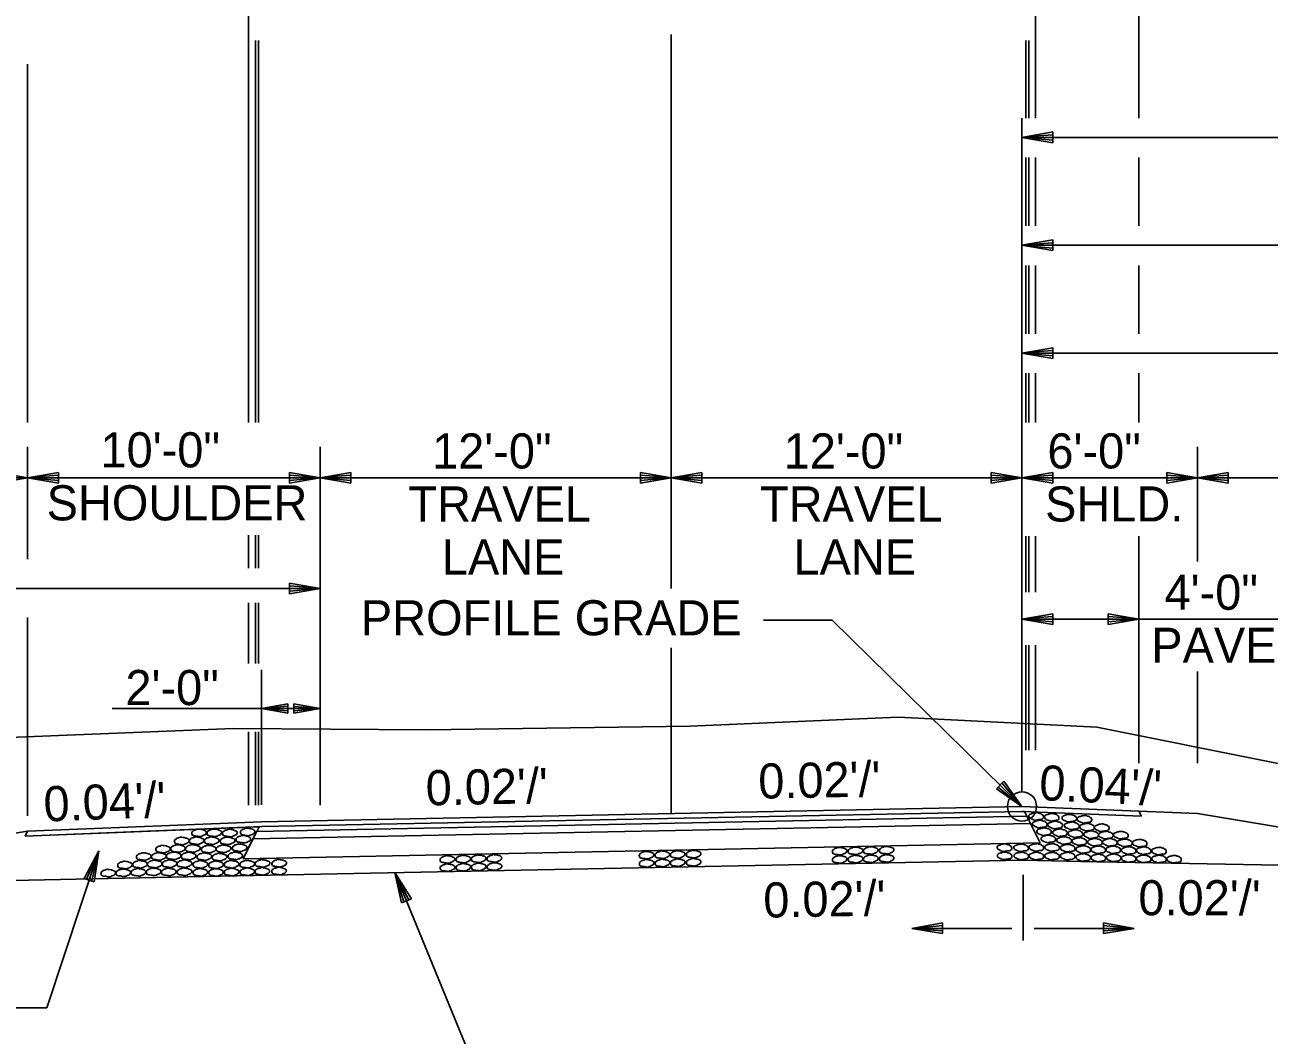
# Model space of a CAD drawing. Extents: x 1734743 to 1735935, y 759845 to 763831.
# Drawn here: x 1735683.61 to 1735726.15, y 763223.34 to 763257.86 of the extents above; entities that cross this region are included whole.
import ezdxf

# ---------------------------------------------------------------- set-up
doc = ezdxf.new("R2010")
doc.units = 0
for name, color, linetype in [('1', 7, 'Continuous'), ('19', 7, 'Continuous'), ('8', 7, 'Continuous'), ('Level 1', 7, 'Continuous'), ('R_Prop Surface', 7, 'Continuous')]:
    doc.layers.add(name, color=color, linetype=linetype)

# ---------------------------------------------------------------- blocks, each defined once
blk = doc.blocks.new('TM')
at = {"layer": '8'}
for p, q in [((-120.309, 21.181), (-119.787, -20.829)), ((0, 0), (-120.309, 21.181)), ((-31.382, 2.945), (-120.176, 10.512)), ((-119.787, -20.829), (0, 0)), ((-119.911, -10.826), (-31.307, -3.057))]:
    blk.add_line(p, q, dxfattribs=at)
blk = doc.blocks.new('ROCKS')
at = {"layer": '1'}
blk.add_spline([(0.013, 0.06), (0.053, 0.053), (0.107, 0.033), (0.133, 0.013), (0.133, -0.007), (0.12, -0.033), (0.107, -0.04), (0.073, -0.053), (0.033, -0.067), (0.013, -0.067), (-0.02, -0.06), (-0.06, -0.053), (-0.087, -0.047), (-0.113, -0.02), (-0.113, -0.007), (-0.107, 0.02), (-0.087, 0.033), (-0.067, 0.047), (-0.033, 0.053), (-0.02, 0.06), (0.013, 0.06)], degree=3, dxfattribs=at)

msp = doc.modelspace()

# ---------------------------------------------------------------- linework, layer by layer
at = {"layer": '19'}
for p, q in [((1735721.698, 763254.679), (1735721.698, 763274.832)), ((1735691.257, 763244.271), (1735691.257, 763259.426)), ((1735718.162, 763254.679), (1735718.162, 763259.426)), ((1735705.701, 763238.596), (1735705.701, 763257.533)), ((1735691.486, 763244.271), (1735691.486, 763257.334)), ((1735691.59, 763244.271), (1735691.59, 763257.334)), ((1735717.832, 763254.679), (1735717.832, 763257.334)), ((1735717.936, 763254.679), (1735717.936, 763257.334)), ((1735683.701, 763244.271), (1735683.701, 763256.522)), ((1735717.701, 763246.647), (1735717.701, 763254.679)), ((1735718.751, 763254.204), (1735717.701, 763254.02)), ((1735718.751, 763254.107), (1735717.981, 763254.046)), ((1735718.751, 763253.836), (1735718.751, 763254.204)), ((1735717.701, 763254.02), (1735797.701, 763254.02)), ((1735717.701, 763254.02), (1735718.751, 763253.836)), ((1735717.981, 763253.994), (1735718.751, 763253.924)), ((1735717.832, 763250.993), (1735717.832, 763253.332)), ((1735717.936, 763250.993), (1735717.936, 763253.332)), ((1735718.162, 763250.993), (1735718.162, 763253.332)), ((1735721.698, 763250.993), (1735721.698, 763253.332)), ((1735718.751, 763250.517), (1735717.701, 763250.333)), ((1735717.701, 763250.333), (1735718.751, 763250.149)), ((1735717.701, 763250.333), (1735757.701, 763250.333)), ((1735718.751, 763250.421), (1735717.981, 763250.359)), ((1735717.981, 763250.307), (1735718.751, 763250.237)), ((1735718.751, 763250.149), (1735718.751, 763250.517)), ((1735717.832, 763247.306), (1735717.832, 763249.645)), ((1735717.936, 763247.306), (1735717.936, 763249.645)), ((1735718.162, 763247.306), (1735718.162, 763249.645)), ((1735721.698, 763247.306), (1735721.698, 763249.645)), ((1735718.751, 763246.83), (1735717.701, 763246.647)), ((1735717.701, 763231.674), (1735717.701, 763246.647)), ((1735717.701, 763246.647), (1735718.751, 763246.463)), ((1735717.701, 763246.647), (1735747.701, 763246.647)), ((1735718.751, 763246.734), (1735717.981, 763246.673)), ((1735717.981, 763246.62), (1735718.751, 763246.55)), ((1735718.751, 763246.463), (1735718.751, 763246.83)), ((1735717.832, 763244.271), (1735717.832, 763245.958)), ((1735717.936, 763244.271), (1735717.936, 763245.958)), ((1735718.162, 763244.271), (1735718.162, 763245.958)), ((1735721.698, 763244.271), (1735721.698, 763245.958)), ((1735683.701, 763239.604), (1735683.701, 763243.437)), ((1735693.701, 763231.194), (1735693.701, 763243.437)), ((1735723.701, 763239.527), (1735723.701, 763243.437)), ((1735672.289, 763242.387), (1735683.701, 763242.387)), ((1735683.701, 763242.387), (1735682.651, 763242.571)), ((1735682.651, 763242.203), (1735683.701, 763242.387)), ((1735684.751, 763242.571), (1735683.701, 763242.387)), ((1735683.701, 763242.387), (1735693.701, 763242.387)), ((1735683.701, 763242.387), (1735684.751, 763242.203)), ((1735684.751, 763242.474), (1735683.981, 763242.413)), ((1735683.981, 763242.361), (1735684.751, 763242.291)), ((1735684.751, 763242.203), (1735684.751, 763242.571)), ((1735692.651, 763242.571), (1735692.651, 763242.203)), ((1735693.701, 763242.387), (1735692.651, 763242.571)), ((1735693.421, 763242.413), (1735692.651, 763242.475)), ((1735692.651, 763242.203), (1735693.701, 763242.387)), ((1735692.651, 763242.291), (1735693.421, 763242.361)), ((1735694.751, 763242.571), (1735693.701, 763242.387)), ((1735693.701, 763242.387), (1735705.701, 763242.387)), ((1735693.701, 763242.387), (1735694.751, 763242.203)), ((1735694.751, 763242.474), (1735693.981, 763242.413)), ((1735693.981, 763242.361), (1735694.751, 763242.291)), ((1735694.751, 763242.203), (1735694.751, 763242.571)), ((1735704.651, 763242.571), (1735704.651, 763242.203)), ((1735705.701, 763242.387), (1735704.651, 763242.571)), ((1735705.421, 763242.413), (1735704.651, 763242.475)), ((1735704.651, 763242.203), (1735705.701, 763242.387)), ((1735704.651, 763242.291), (1735705.421, 763242.361)), ((1735706.751, 763242.571), (1735705.701, 763242.387)), ((1735705.701, 763242.387), (1735717.701, 763242.387)), ((1735705.701, 763242.387), (1735706.751, 763242.203)), ((1735706.751, 763242.474), (1735705.981, 763242.413)), ((1735705.981, 763242.361), (1735706.751, 763242.291)), ((1735706.751, 763242.203), (1735706.751, 763242.571)), ((1735716.651, 763242.571), (1735716.651, 763242.203)), ((1735717.701, 763242.387), (1735716.651, 763242.571)), ((1735717.421, 763242.413), (1735716.651, 763242.475)), ((1735716.651, 763242.203), (1735717.701, 763242.387)), ((1735716.651, 763242.291), (1735717.421, 763242.361)), ((1735718.751, 763242.571), (1735717.701, 763242.387)), ((1735717.701, 763242.387), (1735723.701, 763242.387)), ((1735717.701, 763242.387), (1735718.751, 763242.203)), ((1735718.751, 763242.474), (1735717.981, 763242.413)), ((1735717.981, 763242.361), (1735718.751, 763242.291)), ((1735718.751, 763242.203), (1735718.751, 763242.571)), ((1735722.651, 763242.571), (1735722.651, 763242.203)), ((1735723.701, 763242.387), (1735722.651, 763242.571)), ((1735723.421, 763242.413), (1735722.651, 763242.475)), ((1735722.651, 763242.203), (1735723.701, 763242.387)), ((1735722.651, 763242.291), (1735723.421, 763242.361)), ((1735724.751, 763242.571), (1735723.701, 763242.387)), ((1735723.701, 763242.387), (1735735.382, 763242.387)), ((1735723.701, 763242.387), (1735724.751, 763242.203)), ((1735724.751, 763242.474), (1735723.981, 763242.413)), ((1735723.981, 763242.361), (1735724.751, 763242.291)), ((1735724.751, 763242.203), (1735724.751, 763242.571)), ((1735691.257, 763239.292), (1735691.257, 763240.42)), ((1735691.486, 763239.292), (1735691.486, 763240.42)), ((1735691.59, 763239.292), (1735691.59, 763240.42)), ((1735717.832, 763238.472), (1735717.832, 763240.391)), ((1735717.936, 763238.472), (1735717.936, 763240.391)), ((1735718.162, 763238.472), (1735718.162, 763240.391)), ((1735721.698, 763232.626), (1735721.698, 763240.391)), ((1735692.651, 763238.788), (1735692.651, 763238.421)), ((1735693.701, 763238.604), (1735692.651, 763238.788)), ((1735663.701, 763238.604), (1735693.701, 763238.604)), ((1735693.421, 763238.631), (1735692.651, 763238.692)), ((1735692.651, 763238.421), (1735693.701, 763238.604)), ((1735692.651, 763238.508), (1735693.421, 763238.578)), ((1735691.257, 763236.041), (1735691.257, 763238.111)), ((1735691.486, 763236.041), (1735691.486, 763238.111)), ((1735691.59, 763236.041), (1735691.59, 763238.111)), ((1735683.701, 763230.834), (1735683.701, 763237.604)), ((1735718.751, 763237.739), (1735717.701, 763237.555)), ((1735717.701, 763237.555), (1735727.808, 763237.555)), ((1735717.701, 763237.555), (1735718.751, 763237.372)), ((1735718.751, 763237.643), (1735717.981, 763237.582)), ((1735717.981, 763237.529), (1735718.751, 763237.459)), ((1735718.751, 763237.372), (1735718.751, 763237.739)), ((1735720.648, 763237.739), (1735720.648, 763237.372)), ((1735721.698, 763237.555), (1735720.648, 763237.739)), ((1735721.418, 763237.582), (1735720.648, 763237.643)), ((1735720.648, 763237.372), (1735721.698, 763237.555)), ((1735720.648, 763237.459), (1735721.418, 763237.529)), ((1735717.832, 763233.07), (1735717.832, 763236.66)), ((1735717.936, 763233.07), (1735717.936, 763236.66)), ((1735718.162, 763233.07), (1735718.162, 763236.66)), ((1735705.701, 763230.909), (1735705.701, 763236.572)), ((1735691.701, 763231.201), (1735691.701, 763235.816)), ((1735723.701, 763232.626), (1735723.701, 763235.765)), ((1735692.595, 763234.655), (1735691.701, 763234.498)), ((1735692.595, 763234.58), (1735691.939, 763234.52)), ((1735692.595, 763234.341), (1735692.595, 763234.655)), ((1735692.806, 763234.655), (1735692.806, 763234.342)), ((1735693.701, 763234.498), (1735692.806, 763234.655)), ((1735693.462, 763234.52), (1735692.806, 763234.573)), ((1735686.593, 763234.498), (1735693.701, 763234.498)), ((1735691.701, 763234.498), (1735692.595, 763234.341)), ((1735691.939, 763234.476), (1735692.595, 763234.423)), ((1735692.806, 763234.342), (1735693.701, 763234.498)), ((1735692.806, 763234.416), (1735693.462, 763234.476)), ((1735691.257, 763231.194), (1735691.257, 763233.702)), ((1735691.486, 763231.194), (1735691.486, 763233.702)), ((1735691.59, 763231.194), (1735691.59, 763233.702)), ((1735691.59, 763231.194), (1735691.59, 763233.702)), ((1735717.079, 763232.015), (1735716.826, 763231.753)), ((1735717.701, 763231.149), (1735717.079, 763232.015)), ((1735716.826, 763231.753), (1735717.701, 763231.149)), ((1735716.887, 763231.814), (1735717.482, 763231.324)), ((1735717.517, 763231.359), (1735717.018, 763231.945)), ((1735717.701, 763231.149), (1735691.701, 763230.629)), ((1735717.701, 763231.149), (1735723.701, 763230.909)), ((1735717.866, 763230.819), (1735691.532, 763230.292)), ((1735717.866, 763230.819), (1735691.532, 763230.292)), ((1735717.702, 763230.982), (1735691.706, 763230.462)), ((1735717.702, 763230.982), (1735721.783, 763230.819)), ((1735717.99, 763230.571), (1735717.866, 763230.819)), ((1735723.701, 763230.909), (1735735.382, 763228.962)), ((1735683.701, 763230.309), (1735663.701, 763226.976)), ((1735691.706, 763230.462), (1735683.616, 763230.139)), ((1735691.701, 763230.629), (1735683.701, 763230.309)), ((1735691.701, 763230.629), (1735683.701, 763230.309)), ((1735717.99, 763230.571), (1735691.406, 763230.04)), ((1735691.406, 763230.04), (1735717.99, 763230.571)), ((1735717.99, 763230.571), (1735691.406, 763230.04)), ((1735691.532, 763230.292), (1735691.406, 763230.04)), ((1735718.32, 763229.911), (1735717.99, 763230.571)), ((1735691.406, 763230.04), (1735691.069, 763229.366)), ((1735718.32, 763229.911), (1735691.069, 763229.366)), ((1735691.069, 763229.366), (1735718.32, 763229.911)), ((1735684.354, 763224.268), (1735686.139, 763229.629)), ((1735685.635, 763228.693), (1735686.139, 763229.629)), ((1735686.139, 763229.629), (1735685.98, 763228.574)), ((1735685.717, 763228.666), (1735686.024, 763229.373)), ((1735686.071, 763229.358), (1735685.894, 763228.609)), ((1735717.718, 763229.315), (1735689.719, 763228.755)), ((1735717.718, 763229.315), (1735719.718, 763229.275)), ((1735719.718, 763229.275), (1735735.382, 763228.962)), ((1735689.719, 763228.755), (1735672.288, 763228.407)), ((1735685.98, 763228.574), (1735685.635, 763228.693)), ((1735696.255, 763228.894), (1735700.888, 763217.625)), ((1735696.485, 763227.856), (1735696.255, 763228.894)), ((1735696.255, 763228.894), (1735696.823, 763227.992)), ((1735696.564, 763227.889), (1735696.335, 763228.625)), ((1735696.38, 763228.644), (1735696.735, 763227.961)), ((1735717.737, 763228.818), (1735717.737, 763226.564)), ((1735696.823, 763227.992), (1735696.485, 763227.856)), ((1735717.359, 763226.981), (1735713.938, 763226.981)), ((1735718.116, 763226.981), (1735721.537, 763226.981)), ((1735679.818, 763224.268), (1735684.354, 763224.268))]:
    msp.add_line(p, q, dxfattribs=at)
for points in [[(1735708.857, 763237.517), (1735711.212, 763237.517), (1735717.701, 763231.149)], [(1735623.038, 763233.28), (1735659.802, 763233.52), (1735671.351, 763233.86), (1735675.305, 763233.358), (1735680.786, 763233.418), (1735690.726, 763233.814), (1735697.359, 763233.773), (1735706.351, 763233.895), (1735713.47, 763234.2)], [(1735713.47, 763234.2), (1735720.263, 763233.86), (1735732.151, 763231.48), (1735745.738, 763226.38), (1735755.142, 763225.124)], [(1735721.783, 763230.819), (1735717.702, 763230.982), (1735691.706, 763230.462), (1735691.616, 763230.459), (1735691.616, 763230.459), (1735683.616, 763230.139), (1735683.701, 763230.309), (1735683.701, 763230.309), (1735691.701, 763230.629), (1735717.701, 763231.149), (1735721.698, 763230.989), (1735721.698, 763230.989), (1735721.783, 763230.819), (1735721.783, 763230.819), (1735721.783, 763230.819)], [(1735717.866, 763230.819), (1735691.532, 763230.292), (1735691.532, 763230.292), (1735691.616, 763230.459), (1735691.616, 763230.459), (1735691.704, 763230.462), (1735717.702, 763230.982), (1735717.786, 763230.979), (1735717.786, 763230.979), (1735717.866, 763230.819), (1735717.866, 763230.819), (1735717.866, 763230.819)]]:
    msp.add_lwpolyline(points, dxfattribs=at)
msp.add_circle((1735717.701, 763231.149), 0.5, dxfattribs=at)
at = {"layer": 'R_Prop Surface'}
for p, q in [((1735717.786, 763230.979), (1735718.32, 763229.911)), ((1735721.698, 763230.989), (1735721.783, 763230.819)), ((1735683.701, 763230.309), (1735683.616, 763230.139)), ((1735691.616, 763230.459), (1735691.069, 763229.366))]:
    msp.add_line(p, q, dxfattribs=at)

# ---------------------------------------------------------------- block references
at = {"layer": '19', "xscale": 0.008761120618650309}
for p, yscale, rotation in [((1735713.934, 763226.976), -0.008761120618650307, -179.20057588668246), ((1735721.538, 763226.976), 0.008761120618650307, -0.7994241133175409)]:
    msp.add_blockref('TM', p, dxfattribs=dict(at, yscale=yscale, rotation=rotation))
at = {"layer": 'Level 1'}
for p, xscale, yscale, rotation in [((1735718.206, 763230.815), 2.0116542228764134, -2.011654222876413, 177.9586193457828), ((1735718.738, 763230.786), 2.0116542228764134, -2.011654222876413, 177.9586193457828), ((1735719.338, 763230.756), 2.011654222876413, -2.0116542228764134, 177.95871721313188), ((1735719.857, 763230.717), 2.011654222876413, -2.0116542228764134, 177.95871721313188), ((1735689.542, 763230.255), 2.011654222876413, 2.0116542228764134, 2.041282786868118), ((1735690.061, 763230.255), 2.011654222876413, 2.0116542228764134, 2.041282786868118), ((1735690.593, 763230.249), 2.011654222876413, 2.0116542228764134, 2.041282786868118), ((1735691.203, 763230.285), 2.011654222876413, 2.0116542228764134, 2.041282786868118), ((1735718.33, 763230.556), 2.0116542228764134, -2.011654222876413, 177.9586193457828), ((1735718.475, 763230.295), 2.0116542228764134, -2.011654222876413, 177.9586193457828), ((1735718.856, 763230.522), 2.0116542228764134, -2.011654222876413, 177.9586193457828), ((1735719.02, 763230.26), 2.0116542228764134, -2.011654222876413, 177.9586193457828), ((1735719.425, 763230.495), 2.011654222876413, -2.0116542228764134, 177.95871721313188), ((1735719.549, 763230.227), 2.0116542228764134, -2.011654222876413, 177.9586193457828), ((1735719.947, 763230.449), 2.011654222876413, -2.0116542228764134, 177.95871721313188), ((1735720.086, 763230.192), 2.011654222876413, -2.0116542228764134, 177.95871721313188), ((1735720.452, 763230.43), 2.011654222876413, -2.0116542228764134, 177.95871721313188), ((1735720.591, 763230.177), 2.011654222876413, -2.0116542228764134, 177.95871721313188), ((1735721.103, 763230.175), 2.011654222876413, -2.0116542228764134, 177.95871721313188), ((1735688.82, 763229.718), 2.011654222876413, 2.0116542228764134, 2.041282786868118), ((1735688.951, 763229.977), 2.011654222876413, 2.0116542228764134, 2.041282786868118), ((1735689.329, 763229.721), 2.011654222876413, 2.0116542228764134, 2.041282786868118), ((1735689.456, 763229.987), 2.011654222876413, 2.0116542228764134, 2.041282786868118), ((1735689.974, 763229.986), 2.011654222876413, 2.0116542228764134, 2.041282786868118), ((1735690.515, 763229.981), 2.011654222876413, 2.0116542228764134, 2.041282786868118), ((1735690.928, 763229.744), 2.011654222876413, 2.0116542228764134, 2.041282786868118), ((1735691.056, 763230.036), 2.011654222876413, 2.0116542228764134, 2.041282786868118), ((1735717.122, 763229.747), 2.0116542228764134, -2.011654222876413, 177.9586193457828), ((1735717.692, 763229.745), 2.0116542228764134, -2.011654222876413, 177.9586193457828), ((1735718.215, 763229.757), 2.0116542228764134, -2.011654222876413, 177.9586193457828), ((1735718.622, 763230.047), 2.0116542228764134, -2.011654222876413, 177.9586193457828), ((1735718.751, 763229.755), 2.0116542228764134, -2.011654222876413, 177.9586193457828), ((1735719.164, 763229.992), 2.0116542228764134, -2.011654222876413, 177.9586193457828), ((1735719.285, 763229.73), 2.0116542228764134, -2.011654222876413, 177.9586193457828), ((1735719.685, 763229.959), 2.0116542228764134, -2.011654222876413, 177.9586193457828), ((1735720.216, 763229.934), 2.011654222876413, -2.0116542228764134, 177.95871721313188), ((1735720.726, 763229.929), 2.011654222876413, -2.0116542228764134, 177.95871721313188), ((1735721.238, 763229.913), 2.011654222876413, -2.0116542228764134, 177.95871721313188), ((1735721.747, 763229.901), 2.011654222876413, -2.0116542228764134, 177.95871721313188), ((1735687.652, 763229.444), 2.011654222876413, 2.0116542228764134, 2.041282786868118), ((1735688.165, 763229.449), 2.011654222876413, 2.0116542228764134, 2.041282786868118), ((1735688.308, 763229.7), 2.011654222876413, 2.0116542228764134, 2.041282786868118), ((1735688.674, 763229.468), 2.011654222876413, 2.0116542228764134, 2.041282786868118), ((1735689.183, 763229.462), 2.011654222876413, 2.0116542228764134, 2.041282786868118), ((1735689.724, 763229.443), 2.011654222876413, 2.0116542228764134, 2.041282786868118), ((1735689.87, 763229.699), 2.011654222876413, 2.0116542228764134, 2.041282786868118), ((1735690.239, 763229.425), 2.011654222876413, 2.0116542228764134, 2.041282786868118), ((1735690.376, 763229.709), 2.011654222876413, 2.0116542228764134, 2.041282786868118), ((1735690.781, 763229.466), 2.011654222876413, 2.0116542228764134, 2.041282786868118), ((1735698.034, 763229.345), 2.011654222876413, 2.0116542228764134, 3.0987721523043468), ((1735698.577, 763229.357), 2.011654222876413, 2.0116542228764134, 3.0987721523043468), ((1735699.099, 763229.369), 2.011654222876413, 2.0116542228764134, 3.0987721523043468), ((1735699.641, 763229.381), 2.011654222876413, 2.0116542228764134, 3.0987721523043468), ((1735704.842, 763229.492), 2.011654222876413, 2.0116542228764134, 3.0987721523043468), ((1735705.385, 763229.504), 2.011654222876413, 2.0116542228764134, 3.0987721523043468), ((1735705.907, 763229.516), 2.011654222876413, 2.0116542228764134, 3.0987721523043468), ((1735706.45, 763229.528), 2.011654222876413, 2.0116542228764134, 3.0987721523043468), ((1735711.444, 763229.626), 2.011654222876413, 2.0116542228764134, 3.0987721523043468), ((1735711.445, 763229.346), 2.011654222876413, 2.0116542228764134, 3.0987721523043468), ((1735711.987, 763229.638), 2.011654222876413, 2.0116542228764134, 3.0987721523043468), ((1735711.988, 763229.358), 2.011654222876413, 2.0116542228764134, 3.0987721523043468), ((1735712.509, 763229.649), 2.011654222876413, 2.0116542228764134, 3.0987721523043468), ((1735712.51, 763229.369), 2.011654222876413, 2.0116542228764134, 3.0987721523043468), ((1735713.051, 763229.661), 2.011654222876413, 2.0116542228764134, 3.0987721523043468), ((1735713.052, 763229.381), 2.011654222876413, 2.0116542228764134, 3.0987721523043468), ((1735717.126, 763229.467), 2.0116542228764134, -2.011654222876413, 177.9586193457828), ((1735717.696, 763229.465), 2.0116542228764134, -2.011654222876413, 177.9586193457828), ((1735718.214, 763229.463), 2.0116542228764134, -2.011654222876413, 177.9586193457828), ((1735718.75, 763229.461), 2.0116542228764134, -2.011654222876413, 177.9586193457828), ((1735719.284, 763229.459), 2.0116542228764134, -2.011654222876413, 177.9586193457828), ((1735719.817, 763229.413), 2.0116542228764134, -2.011654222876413, 177.9586193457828), ((1735719.818, 763229.684), 2.0116542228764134, -2.011654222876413, 177.9586193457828), ((1735720.333, 763229.677), 2.011654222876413, -2.0116542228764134, 177.95871721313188), ((1735720.333, 763229.397), 2.011654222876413, -2.0116542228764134, 177.95871721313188), ((1735720.844, 763229.677), 2.011654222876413, -2.0116542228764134, 177.95871721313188), ((1735720.857, 763229.401), 2.011654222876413, -2.0116542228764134, 177.95871721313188), ((1735721.371, 763229.652), 2.011654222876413, -2.0116542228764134, 177.95871721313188), ((1735721.371, 763229.377), 2.011654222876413, -2.0116542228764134, 177.95871721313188), ((1735721.884, 763229.646), 2.011654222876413, -2.0116542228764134, 177.95871721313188), ((1735721.884, 763229.366), 2.011654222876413, -2.0116542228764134, 177.95871721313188), ((1735722.409, 763229.632), 2.011654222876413, -2.0116542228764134, 177.95871721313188), ((1735722.409, 763229.361), 2.011654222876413, -2.0116542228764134, 177.95871721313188), ((1735722.922, 763229.353), 2.011654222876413, -2.0116542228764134, 177.95871721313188), ((1735686.437, 763228.879), 2.011654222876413, 2.0116542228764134, 2.041282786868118), ((1735686.95, 763228.89), 2.011654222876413, 2.0116542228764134, 2.041282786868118), ((1735687.006, 763229.155), 2.011654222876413, 2.0116542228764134, 2.041282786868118), ((1735687.467, 763228.906), 2.011654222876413, 2.0116542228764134, 2.041282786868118), ((1735687.522, 763229.181), 2.011654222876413, 2.0116542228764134, 2.041282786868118), ((1735687.986, 763228.921), 2.011654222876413, 2.0116542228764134, 2.041282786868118), ((1735688.026, 763229.191), 2.011654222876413, 2.0116542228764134, 2.041282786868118), ((1735688.504, 763228.917), 2.011654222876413, 2.0116542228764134, 2.041282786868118), ((1735688.532, 763229.2), 2.011654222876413, 2.0116542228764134, 2.041282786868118), ((1735689.042, 763229.201), 2.011654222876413, 2.0116542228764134, 2.041282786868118), ((1735689.042, 763228.925), 2.011654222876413, 2.0116542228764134, 2.041282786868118), ((1735689.585, 763229.177), 2.011654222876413, 2.0116542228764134, 2.041282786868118), ((1735689.586, 763228.906), 2.011654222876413, 2.0116542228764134, 2.041282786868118), ((1735690.118, 763229.162), 2.011654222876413, 2.0116542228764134, 2.041282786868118), ((1735690.119, 763228.901), 2.011654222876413, 2.0116542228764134, 2.041282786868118), ((1735690.652, 763229.181), 2.011654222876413, 2.0116542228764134, 2.041282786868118), ((1735690.653, 763228.916), 2.011654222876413, 2.0116542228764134, 2.041282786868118), ((1735691.187, 763229.183), 2.011654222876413, 2.0116542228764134, 2.041282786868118), ((1735691.189, 763228.927), 2.011654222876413, 2.0116542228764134, 2.041282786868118), ((1735691.707, 763228.939), 2.011654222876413, 2.0116542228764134, 2.041282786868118), ((1735691.711, 763229.209), 2.011654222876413, 2.0116542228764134, 2.041282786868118), ((1735692.277, 763228.949), 2.011654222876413, 2.0116542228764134, 2.041282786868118), ((1735692.281, 763229.214), 2.011654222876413, 2.0116542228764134, 2.041282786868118), ((1735698.035, 763229.065), 2.011654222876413, 2.0116542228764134, 3.0987721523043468), ((1735698.578, 763229.077), 2.011654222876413, 2.0116542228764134, 3.0987721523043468), ((1735699.1, 763229.089), 2.011654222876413, 2.0116542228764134, 3.0987721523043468), ((1735699.642, 763229.101), 2.011654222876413, 2.0116542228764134, 3.0987721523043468), ((1735704.843, 763229.212), 2.011654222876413, 2.0116542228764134, 3.0987721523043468), ((1735705.386, 763229.224), 2.011654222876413, 2.0116542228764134, 3.0987721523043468), ((1735705.908, 763229.236), 2.011654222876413, 2.0116542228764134, 3.0987721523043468), ((1735706.451, 763229.248), 2.011654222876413, 2.0116542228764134, 3.0987721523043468)]:
    msp.add_blockref('ROCKS', p, dxfattribs=dict(at, xscale=xscale, yscale=yscale, rotation=rotation))

# ---------------------------------------------------------------- texts
at = {"layer": '19'}
for s, p in [('10\'-0"', (1735686.192, 763242.741)), ('12\'-0"', (1735697.529, 763242.702)), ('12\'-0"', (1735709.552, 763242.702)), ('6\'-0"', (1735718.57, 763242.704)), ('SHOULDER', (1735684.35, 763240.929)), ('TRAVEL', (1735696.721, 763240.89)), ('TRAVEL', (1735708.744, 763240.89)), ('SHLD.', (1735718.49, 763240.891)), ('LANE', (1735697.865, 763239.077)), ('LANE', (1735709.888, 763239.077)), ('4\'-0"', (1735722.575, 763237.872)), ('PROFILE GRADE', (1735695.094, 763236.999)), ('PAVED', (1735722.122, 763236.06)), ('2\'-0"', (1735687.043, 763234.616)), ("0.02'/'", (1735721.683, 763227.431))]:
    msp.add_text(s, height=1.2, dxfattribs=at).set_placement(p)
for s, rotation, p in [("0.02'/'", 1.0931, (1735697.321, 763231.185)), ("0.02'/'", 1.0931, (1735708.695, 763231.415)), ("0.04'/'", 357.3887, (1735718.273, 763231.369)), ("0.04'/'", 2.1602, (1735684.266, 763230.633)), ("0.02'/'", 1.0121, (1735708.865, 763227.349))]:
    msp.add_text(s, height=1.2, rotation=rotation, dxfattribs=at).set_placement(p)

doc.saveas('drawing.dxf')
